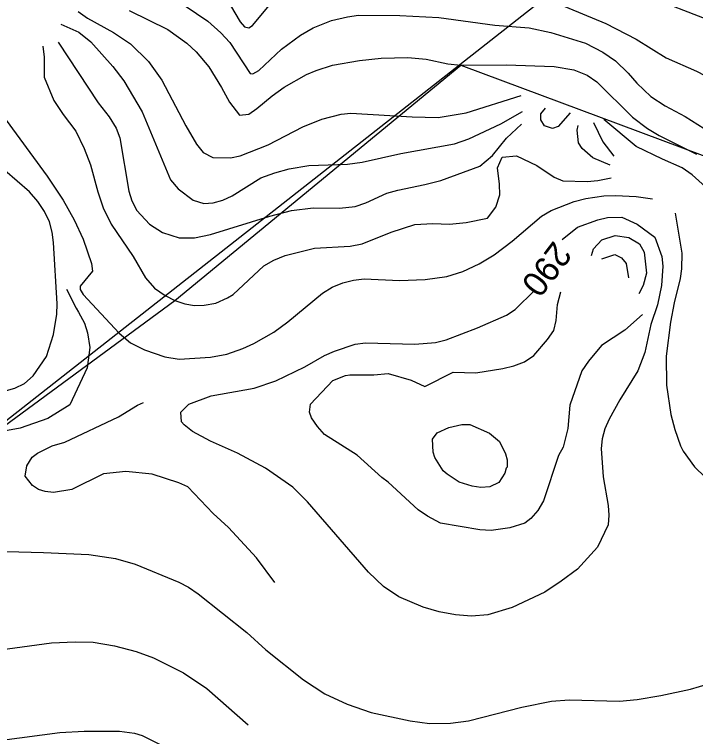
# Model space of a CAD drawing. Extents: x -662620 to -656370, y -1067090 to -1062990.
# Drawn here: x -661471.5 to -661109.4, y -1065594.8 to -1065210.9 of the extents above; entities that cross this region are included whole.
import ezdxf

# ---------------------------------------------------------------- set-up
doc = ezdxf.new("R2010")
doc.units = 0
for name, color, linetype in [('CHRANENE_LOZISKOVE_UZEMI', 7, 'Continuous'), ('HRANICE_KATASTRÁLNÍHO_ÚZEMÍ', 7, 'Continuous'), ('VRSTEVNICE_ZDŮRAZNĚNÁ', 7, 'Continuous'), ('VRSTEVNICE_ZDŮRAZNĚNÁ_-_POPIS', 7, 'Continuous'), ('VRSTEVNICE_ZÁKLADNÍ', 7, 'Continuous')]:
    doc.layers.add(name, color=color, linetype=linetype)

msp = doc.modelspace()

# ---------------------------------------------------------------- linework, layer by layer
at = {"layer": 'CHRANENE_LOZISKOVE_UZEMI'}
msp.add_lwpolyline([(-661096.57, -1065944.42), (-661652.65, -1065558.91), (-661386.13, -1065362.86), (-661234.18, -1065237.85), (-660862.53, -1065376.49), (-660732.31, -1065445.66), (-660264.34, -1065722.38)], dxfattribs=at)
at = {"layer": 'HRANICE_KATASTRÁLNÍHO_ÚZEMÍ'}
msp.add_lwpolyline([(-661678.37, -1065578.57), (-661652.65, -1065558.91), (-661530.81, -1065469.36), (-661523.21, -1065463.74), (-661084.87, -1065119.64)], dxfattribs=at)
at = {"layer": 'VRSTEVNICE_ZDŮRAZNĚNÁ'}
for points in [[(-661437.6, -1065209.33), (-661432.58, -1065212.77), (-661418.82, -1065220.51), (-661409.79, -1065226.53), (-661400.18, -1065235.85), (-661393.16, -1065245.74), (-661380.4, -1065270.11), (-661374.67, -1065279.86), (-661371.08, -1065284.3), (-661366.07, -1065286.88), (-661356.6, -1065287.17), (-661351.44, -1065286.02), (-661336.53, -1065280.14), (-661318.19, -1065270.68), (-661308.15, -1065266.53), (-661297.83, -1065263.8), (-661292.67, -1065263.37), (-661259.98, -1065265.38), (-661246.22, -1065265.67), (-661231.31, -1065263.23), (-661202.11, -1065254.02)], [(-661058.2, -1065396.19), (-661068.47, -1065386.44), (-661085.38, -1065351.53), (-661091.66, -1065335.79), (-661096.46, -1065319.61), (-661102.37, -1065304.17), (-661111.18, -1065296.06), (-661116.49, -1065292.33), (-661126.95, -1065287.89), (-661140.99, -1065281.09), (-661158.21, -1065266.68)], [(-661477.02, -1065411.17), (-661471.29, -1065409.59), (-661466.13, -1065407.01), (-661461.54, -1065403), (-661454.51, -1065392.68), (-661450.79, -1065381.07), (-661448.92, -1065370.17), (-661448.78, -1065364.72), (-661450.64, -1065332.04), (-661451.36, -1065326.59), (-661452.79, -1065321.14), (-661455.52, -1065315.7), (-661458.96, -1065310.25), (-661463.55, -1065305.09), (-661483.33, -1065288.17)], [(-661180.24, -1065330.57), (-661172.19, -1065323.92), (-661161.36, -1065320), (-661156.2, -1065318.85), (-661148.6, -1065318.71), (-661140.43, -1065322.29), (-661131.11, -1065329.31), (-661127.38, -1065339.49), (-661126.81, -1065344.65), (-661127.52, -1065354.98), (-661129.67, -1065365.3), (-661133.11, -1065375.62), (-661136.41, -1065390.53), (-661140, -1065400.27), (-661149.6, -1065415.76), (-661155.34, -1065426.08), (-661157.63, -1065431.24), (-661159.06, -1065436.4), (-661159.64, -1065441.56), (-661158.49, -1065456.76), (-661155.91, -1065471.95), (-661155.48, -1065477.11), (-661155.77, -1065482.27), (-661161.45, -1065494.1), (-661172.17, -1065505.7), (-661180.85, -1065512.23), (-661189.45, -1065517.97), (-661206.94, -1065526.14), (-661219.84, -1065530.01), (-661228.45, -1065530.73), (-661237.05, -1065530.01), (-661245.65, -1065528.43), (-661254.25, -1065526), (-661267.15, -1065520.55), (-661275.32, -1065514.96), (-661283.35, -1065507.36), (-661315.75, -1065469.94), (-661323.49, -1065462.2), (-661337.97, -1065452.03), (-661352.88, -1065444.14), (-661367.21, -1065437.69), (-661376.82, -1065432.67), (-661381.26, -1065429.09), (-661382.69, -1065427.37), (-661382.99, -1065422.27), (-661378.78, -1065418.06), (-661366.93, -1065413.61), (-661343.99, -1065409.59), (-661332.52, -1065405.72), (-661317.04, -1065398.12), (-661306.57, -1065392.25), (-661301.27, -1065389.81), (-661290.37, -1065386.23), (-661284.93, -1065385.37), (-661258.55, -1065386.23), (-661247.65, -1065385.22), (-661241.92, -1065383.79), (-661225.29, -1065377.48), (-661209.95, -1065370.74), (-661205.22, -1065367.73), (-661194.76, -1065357.41)]]:
    msp.add_lwpolyline(points, dxfattribs=at)
at = {"layer": 'VRSTEVNICE_ZÁKLADNÍ'}
for points in [[(-661189.17, -1065202.16), (-661157.05, -1065215.63), (-661141, -1065224.09), (-661124.94, -1065233.98), (-661108.89, -1065241.01), (-661095.99, -1065247.75), (-661065.17, -1065267.39), (-661059.72, -1065272.4), (-661051.55, -1065282.87), (-661046.02, -1065293.94)], [(-661189.17, -1065202.16), (-661157.05, -1065215.63), (-661141, -1065224.09), (-661124.94, -1065233.98), (-661108.89, -1065241.01), (-661095.99, -1065247.75), (-661065.17, -1065267.39), (-661059.72, -1065272.4), (-661051.55, -1065282.87), (-661046.02, -1065293.94)], [(-661040.29, -1065245.82), (-661048.12, -1065237.81), (-661060.15, -1065229.25), (-661067.89, -1065225.53), (-661102.29, -1065213.91), (-661134.41, -1065201.3)], [(-661040.29, -1065245.82), (-661048.12, -1065237.81), (-661060.15, -1065229.25), (-661067.89, -1065225.53), (-661102.29, -1065213.91), (-661134.41, -1065201.3)], [(-661356.6, -1065206.17), (-661351.44, -1065214.77), (-661349.15, -1065217.5), (-661346.86, -1065217.93), (-661344.99, -1065216.78), (-661334.1, -1065203.74)], [(-661356.6, -1065206.17), (-661351.44, -1065214.77), (-661349.15, -1065217.5), (-661346.86, -1065217.93), (-661344.99, -1065216.78), (-661334.1, -1065203.74)], [(-661410.51, -1065208.75), (-661389.86, -1065218.93), (-661379.83, -1065226.1), (-661374.81, -1065230.83), (-661368.22, -1065238.71), (-661361.33, -1065249.75), (-661357.18, -1065257.49), (-661351.87, -1065264.38), (-661346.86, -1065263.8), (-661342.56, -1065260.93), (-661334.53, -1065254.2), (-661328.08, -1065249.61), (-661316.18, -1065242.87), (-661311.02, -1065240.58), (-661302.42, -1065237.85), (-661288.08, -1065235.27), (-661276.61, -1065234.13), (-661262.28, -1065233.7), (-661252.53, -1065234.7), (-661241.06, -1065237.14), (-661234.18, -1065237.85), (-661210.1, -1065237.57), (-661184.58, -1065238.57), (-661174.18, -1065240.23), (-661167.08, -1065243.19), (-661161.93, -1065246.74), (-661142.86, -1065265.52), (-661134.98, -1065271.54), (-661128.81, -1065275.27), (-661108.89, -1065285.16)], [(-661410.51, -1065208.75), (-661389.86, -1065218.93), (-661379.83, -1065226.1), (-661374.81, -1065230.83), (-661368.22, -1065238.71), (-661361.33, -1065249.75), (-661357.18, -1065257.49), (-661351.87, -1065264.38), (-661346.86, -1065263.8), (-661342.56, -1065260.93), (-661334.53, -1065254.2), (-661328.08, -1065249.61), (-661316.18, -1065242.87), (-661311.02, -1065240.58), (-661302.42, -1065237.85), (-661288.08, -1065235.27), (-661276.61, -1065234.13), (-661262.28, -1065233.7), (-661252.53, -1065234.7), (-661241.06, -1065237.14), (-661234.18, -1065237.85), (-661210.1, -1065237.57), (-661184.58, -1065238.57), (-661174.18, -1065240.23), (-661167.08, -1065243.19), (-661161.93, -1065246.74), (-661142.86, -1065265.52), (-661134.98, -1065271.54), (-661128.81, -1065275.27), (-661108.89, -1065285.16)], [(-661380.69, -1065206.32), (-661368.65, -1065214.49), (-661361.76, -1065220.65), (-661357.03, -1065225.81), (-661346.14, -1065242.3), (-661344.71, -1065242.44), (-661341.55, -1065240.58), (-661329.51, -1065229.4), (-661319.33, -1065221.94), (-661312.59, -1065217.93), (-661302.99, -1065214.06), (-661294.39, -1065212.05), (-661288.65, -1065211.33), (-661266.58, -1065211.48), (-661245.93, -1065212.48), (-661216.12, -1065216.49), (-661197.77, -1065217.93), (-661186.3, -1065220.51), (-661167.95, -1065226.1), (-661158.78, -1065230.97), (-661152.04, -1065235.56), (-661145.16, -1065242.01), (-661140.57, -1065247.32), (-661133.11, -1065254.48), (-661125.52, -1065259.5), (-661114.91, -1065265.09), (-661104.87, -1065271.54)], [(-661380.69, -1065206.32), (-661368.65, -1065214.49), (-661361.76, -1065220.65), (-661357.03, -1065225.81), (-661346.14, -1065242.3), (-661344.71, -1065242.44), (-661341.55, -1065240.58), (-661329.51, -1065229.4), (-661319.33, -1065221.94), (-661312.59, -1065217.93), (-661302.99, -1065214.06), (-661294.39, -1065212.05), (-661288.65, -1065211.33), (-661266.58, -1065211.48), (-661245.93, -1065212.48), (-661216.12, -1065216.49), (-661197.77, -1065217.93), (-661186.3, -1065220.51), (-661167.95, -1065226.1), (-661158.78, -1065230.97), (-661152.04, -1065235.56), (-661145.16, -1065242.01), (-661140.57, -1065247.32), (-661133.11, -1065254.48), (-661125.52, -1065259.5), (-661114.91, -1065265.09), (-661104.87, -1065271.54)], [(-661446.78, -1065216.1), (-661437.23, -1065220.36), (-661430.79, -1065225.47), (-661419.25, -1065238.57), (-661413.37, -1065246.17), (-661403.62, -1065262.66), (-661388.43, -1065298.78), (-661384.41, -1065303.65), (-661376.39, -1065309.54), (-661370.84, -1065311.39), (-661365.78, -1065310.97), (-661360.62, -1065309.68), (-661355.74, -1065307.24), (-661340.41, -1065297.78), (-661333.09, -1065295.05), (-661325.35, -1065292.9), (-661315.03, -1065291.18), (-661294.39, -1065290.47), (-661286.65, -1065289.32), (-661266, -1065284.73), (-661237.62, -1065279.57), (-661229.88, -1065276.99), (-661212.96, -1065268.96), (-661201.39, -1065262.5)], [(-661446.78, -1065216.1), (-661437.23, -1065220.36), (-661430.79, -1065225.47), (-661419.25, -1065238.57), (-661413.37, -1065246.17), (-661403.62, -1065262.66), (-661388.43, -1065298.78), (-661384.41, -1065303.65), (-661376.39, -1065309.54), (-661370.84, -1065311.39), (-661365.78, -1065310.97), (-661360.62, -1065309.68), (-661355.74, -1065307.24), (-661340.41, -1065297.78), (-661333.09, -1065295.05), (-661325.35, -1065292.9), (-661315.03, -1065291.18), (-661294.39, -1065290.47), (-661286.65, -1065289.32), (-661266, -1065284.73), (-661237.62, -1065279.57), (-661229.88, -1065276.99), (-661212.96, -1065268.96), (-661201.39, -1065262.5)], [(-661456.35, -1065227.79), (-661455.61, -1065233.56), (-661455.76, -1065244.22), (-661450.5, -1065256.63), (-661445.63, -1065264.09), (-661438.89, -1065272.98), (-661434.45, -1065282.15), (-661431, -1065290.75), (-661427.13, -1065305.09), (-661424.27, -1065313.69), (-661420.11, -1065322.29), (-661408.35, -1065339.49), (-661401.76, -1065350.96), (-661397.03, -1065356.41), (-661391.29, -1065360.28), (-661386.13, -1065362.86), (-661380.97, -1065364.72), (-661375.81, -1065365.58), (-661370.65, -1065365.44), (-661364.35, -1065364.29), (-661358.18, -1065361.57), (-661355.17, -1065359.71), (-661338.83, -1065344.51), (-661333.67, -1065341.5), (-661327.65, -1065339.06), (-661311.88, -1065335.19), (-661292.96, -1065334.05), (-661286.65, -1065332.9), (-661271.17, -1065326.59), (-661258.55, -1065322.58), (-661249.09, -1065322), (-661240.2, -1065322.43), (-661231.31, -1065321.43), (-661219.99, -1065319.14), (-661215.54, -1065313.26), (-661213.39, -1065306.81), (-661213.54, -1065301.07), (-661214.68, -1065292.47), (-661212.25, -1065286.74), (-661204.65, -1065286.02), (-661193.75, -1065291.18), (-661184.58, -1065297.35), (-661179.99, -1065299.35), (-661167.09, -1065299.64), (-661161.36, -1065299.07), (-661154.24, -1065297.64)], [(-661456.35, -1065227.79), (-661455.61, -1065233.56), (-661455.76, -1065244.22), (-661450.5, -1065256.63), (-661445.63, -1065264.09), (-661438.89, -1065272.98), (-661434.45, -1065282.15), (-661431, -1065290.75), (-661427.13, -1065305.09), (-661424.27, -1065313.69), (-661420.11, -1065322.29), (-661408.35, -1065339.49), (-661401.76, -1065350.96), (-661397.03, -1065356.41), (-661391.29, -1065360.28), (-661386.13, -1065362.86), (-661380.97, -1065364.72), (-661375.81, -1065365.58), (-661370.65, -1065365.44), (-661364.35, -1065364.29), (-661358.18, -1065361.57), (-661355.17, -1065359.71), (-661338.83, -1065344.51), (-661333.67, -1065341.5), (-661327.65, -1065339.06), (-661311.88, -1065335.19), (-661292.96, -1065334.05), (-661286.65, -1065332.9), (-661271.17, -1065326.59), (-661258.55, -1065322.58), (-661249.09, -1065322), (-661240.2, -1065322.43), (-661231.31, -1065321.43), (-661219.99, -1065319.14), (-661215.54, -1065313.26), (-661213.39, -1065306.81), (-661213.54, -1065301.07), (-661214.68, -1065292.47), (-661212.25, -1065286.74), (-661204.65, -1065286.02), (-661193.75, -1065291.18), (-661184.58, -1065297.35), (-661179.99, -1065299.35), (-661167.09, -1065299.64), (-661161.36, -1065299.07), (-661154.24, -1065297.64)], [(-661448.23, -1065225.61), (-661426.99, -1065257.78), (-661421.11, -1065265.24), (-661417.39, -1065271.26), (-661415.52, -1065276.42), (-661410.65, -1065304.8), (-661409.07, -1065309.96), (-661406.49, -1065315.12), (-661399.75, -1065322.43), (-661392.73, -1065326.73), (-661383.84, -1065329.6), (-661375.81, -1065329.6), (-661367.21, -1065327.88), (-661335.67, -1065318.13), (-661324.21, -1065315.12), (-661312.74, -1065313.69), (-661298.69, -1065313.83), (-661290.37, -1065312.97), (-661284.64, -1065310.96), (-661273.46, -1065305.95), (-661267.72, -1065304.23), (-661253.39, -1065301.36), (-661244.79, -1065299.07), (-661224.15, -1065291.61), (-661217.41, -1065285.88), (-661209.95, -1065276.7), (-661201.92, -1065269.11)], [(-661448.23, -1065225.61), (-661426.99, -1065257.78), (-661421.11, -1065265.24), (-661417.39, -1065271.26), (-661415.52, -1065276.42), (-661410.65, -1065304.8), (-661409.07, -1065309.96), (-661406.49, -1065315.12), (-661399.75, -1065322.43), (-661392.73, -1065326.73), (-661383.84, -1065329.6), (-661375.81, -1065329.6), (-661367.21, -1065327.88), (-661335.67, -1065318.13), (-661324.21, -1065315.12), (-661312.74, -1065313.69), (-661298.69, -1065313.83), (-661290.37, -1065312.97), (-661284.64, -1065310.96), (-661273.46, -1065305.95), (-661267.72, -1065304.23), (-661253.39, -1065301.36), (-661244.79, -1065299.07), (-661224.15, -1065291.61), (-661217.41, -1065285.88), (-661209.95, -1065276.7), (-661201.92, -1065269.11)], [(-661176.08, -1065263.19), (-661182.37, -1065270.52), (-661185.4, -1065271.48), (-661189.77, -1065270.11), (-661191.69, -1065266.93), (-661191.62, -1065263.67), (-661189.1, -1065260.71)], [(-661176.08, -1065263.19), (-661182.37, -1065270.52), (-661185.4, -1065271.48), (-661189.77, -1065270.11), (-661191.69, -1065266.93), (-661191.62, -1065263.67), (-661189.1, -1065260.71)], [(-661477.74, -1065264.38), (-661454.08, -1065296.77), (-661445.63, -1065309.68), (-661439.75, -1065320), (-661435.02, -1065330.32), (-661430.57, -1065343.22), (-661430, -1065347.38), (-661436.6, -1065355.4), (-661436.45, -1065357.13), (-661435.02, -1065359.71), (-661415.81, -1065380.35), (-661409.79, -1065385.37), (-661402.33, -1065389.09), (-661391.58, -1065392.82), (-661383.84, -1065394.11), (-661367.21, -1065393.11), (-661358.61, -1065391.53), (-661350.01, -1065388.52), (-661344.28, -1065385.8), (-661333.67, -1065379.77), (-661326.07, -1065374.33), (-661307.72, -1065358.99), (-661302.56, -1065355.84), (-661296.97, -1065353.54), (-661291.23, -1065352.11), (-661285.5, -1065351.39), (-661266.86, -1065352.39), (-661253.1, -1065351.82), (-661241.63, -1065350.1), (-661233.03, -1065347.52), (-661224.43, -1065343.51), (-661216.4, -1065338.63), (-661206.94, -1065331.32), (-661191.32, -1065318.13), (-661186.16, -1065315.12), (-661173.97, -1065310.39), (-661167.66, -1065308.67), (-661158.2, -1065307.24), (-661151.89, -1065307.09), (-661141, -1065307.67), (-661132.33, -1065308.93)], [(-661477.74, -1065264.38), (-661454.08, -1065296.77), (-661445.63, -1065309.68), (-661439.75, -1065320), (-661435.02, -1065330.32), (-661430.57, -1065343.22), (-661430, -1065347.38), (-661436.6, -1065355.4), (-661436.45, -1065357.13), (-661435.02, -1065359.71), (-661415.81, -1065380.35), (-661409.79, -1065385.37), (-661402.33, -1065389.09), (-661391.58, -1065392.82), (-661383.84, -1065394.11), (-661367.21, -1065393.11), (-661358.61, -1065391.53), (-661350.01, -1065388.52), (-661344.28, -1065385.8), (-661333.67, -1065379.77), (-661326.07, -1065374.33), (-661307.72, -1065358.99), (-661302.56, -1065355.84), (-661296.97, -1065353.54), (-661291.23, -1065352.11), (-661285.5, -1065351.39), (-661266.86, -1065352.39), (-661253.1, -1065351.82), (-661241.63, -1065350.1), (-661233.03, -1065347.52), (-661224.43, -1065343.51), (-661216.4, -1065338.63), (-661206.94, -1065331.32), (-661191.32, -1065318.13), (-661186.16, -1065315.12), (-661173.97, -1065310.39), (-661167.66, -1065308.67), (-661158.2, -1065307.24), (-661151.89, -1065307.09), (-661141, -1065307.67), (-661132.33, -1065308.93)], [(-661154.83, -1065291.05), (-661164.08, -1065287.06), (-661169.67, -1065282.15), (-661171.68, -1065279.14), (-661172.25, -1065272.4), (-661171.82, -1065269.97)], [(-661154.83, -1065291.05), (-661164.08, -1065287.06), (-661169.67, -1065282.15), (-661171.68, -1065279.14), (-661172.25, -1065272.4), (-661171.82, -1065269.97)], [(-661163.61, -1065268.3), (-661158.77, -1065278.64), (-661152.84, -1065286.15)], [(-661163.61, -1065268.3), (-661158.77, -1065278.64), (-661152.84, -1065286.15)], [(-661120.27, -1065316.44), (-661116.64, -1065337.83), (-661116.92, -1065346.09), (-661117.63, -1065351.25), (-661120.79, -1065364.15), (-661122.65, -1065374.47), (-661124.94, -1065392.53), (-661124.8, -1065408.02), (-661122.51, -1065423.5), (-661120.5, -1065431.53), (-661117.49, -1065440.13), (-661116.06, -1065442.99), (-661109.89, -1065451.45), (-661104.3, -1065456.9), (-661091.11, -1065467.65), (-661078.23, -1065480.37), (-661069.63, -1065492.12)], [(-661120.27, -1065316.44), (-661116.64, -1065337.83), (-661116.92, -1065346.09), (-661117.63, -1065351.25), (-661120.79, -1065364.15), (-661122.65, -1065374.47), (-661124.94, -1065392.53), (-661124.8, -1065408.02), (-661122.51, -1065423.5), (-661120.5, -1065431.53), (-661117.49, -1065440.13), (-661116.06, -1065442.99), (-661109.89, -1065451.45), (-661104.3, -1065456.9), (-661091.11, -1065467.65), (-661078.23, -1065480.37), (-661069.63, -1065492.12)], [(-661164.63, -1065338.97), (-661163.74, -1065335.45), (-661159.23, -1065330.64), (-661152.05, -1065328.35), (-661144.95, -1065329.46), (-661139.17, -1065332.75), (-661136.73, -1065337.19), (-661135.55, -1065348.44), (-661137.17, -1065354.99), (-661139.54, -1065359.36)], [(-661164.63, -1065338.97), (-661163.74, -1065335.45), (-661159.23, -1065330.64), (-661152.05, -1065328.35), (-661144.95, -1065329.46), (-661139.17, -1065332.75), (-661136.73, -1065337.19), (-661135.55, -1065348.44), (-661137.17, -1065354.99), (-661139.54, -1065359.36)], [(-661159.31, -1065340.71), (-661152.35, -1065338.49), (-661148.8, -1065340.34), (-661146.21, -1065343.23), (-661145.09, -1065350.92)], [(-661159.31, -1065340.71), (-661152.35, -1065338.49), (-661148.8, -1065340.34), (-661146.21, -1065343.23), (-661145.09, -1065350.92)], [(-661443.72, -1065356.84), (-661438.68, -1065367.06), (-661437.45, -1065369.17), (-661434.3, -1065375.05), (-661432.58, -1065380.21), (-661431.43, -1065387.95), (-661432.87, -1065398.7), (-661442.01, -1065418.35), (-661453.78, -1065425.72), (-661468.42, -1065430.81), (-661483.19, -1065433.53), (-661500.99, -1065440.82), (-661516.75, -1065441.6), (-661542.25, -1065440.41)], [(-661137.69, -1065370.33), (-661147.01, -1065378.77), (-661159.35, -1065386.94), (-661166.23, -1065395.11), (-661169.81, -1065400.42), (-661176.22, -1065418.66), (-661177.27, -1065430.95), (-661179.7, -1065440.99), (-661182.29, -1065445.43), (-661190.17, -1065469.37), (-661193.32, -1065474.53), (-661197.05, -1065478.83), (-661200.2, -1065481.27), (-661208.09, -1065483.85), (-661218.12, -1065485.14), (-661224.15, -1065484.85), (-661244.95, -1065481.34), (-661251.95, -1065477.54), (-661256.83, -1065474.25), (-661272.74, -1065459.48), (-661276.18, -1065457.04), (-661289.32, -1065445.24), (-661306.57, -1065434.11), (-661310.44, -1065429.95), (-661313.6, -1065425.36), (-661314.6, -1065422.35), (-661314.17, -1065418.05), (-661302.27, -1065405.48), (-661295.53, -1065402.86), (-661293.24, -1065402.43), (-661280.34, -1065402.43), (-661272.8, -1065401.73), (-661260.51, -1065405.21), (-661253.24, -1065408.59), (-661238.19, -1065401), (-661226.27, -1065401.48), (-661211.82, -1065399.13), (-661206.08, -1065397.7), (-661200.35, -1065395.54), (-661195.33, -1065392.25), (-661188.02, -1065383.65), (-661184.72, -1065378.92), (-661183.58, -1065373.61), (-661182.71, -1065365.01), (-661180.99, -1065358.27)], [(-661333.1, -1065512.88), (-661342.84, -1065499.76), (-661357.61, -1065483.71), (-661365.92, -1065476.25), (-661379.28, -1065462.08), (-661384.13, -1065459.91), (-661398.18, -1065455.32), (-661412.22, -1065453.89), (-661424.12, -1065455.04), (-661440.89, -1065463.44), (-661450.64, -1065464.93), (-661455.23, -1065464.5), (-661458.67, -1065463.49), (-661461.83, -1065461.34), (-661465.79, -1065456.35), (-661464.9, -1065450.8), (-661462.11, -1065446.29), (-661459.24, -1065444.14), (-661451.36, -1065440.27), (-661444.62, -1065438.26), (-661416.24, -1065424.79), (-661406.06, -1065418.63), (-661402.91, -1065417.19)], [(-661248.8, -1065443.57), (-661249.23, -1065436.69), (-661246.83, -1065433.32), (-661240.54, -1065430.51), (-661233.61, -1065428.95), (-661229.45, -1065428.8), (-661218.98, -1065433.53), (-661213.68, -1065437.98), (-661210.38, -1065444.43), (-661209.52, -1065447.58), (-661209.52, -1065451.6), (-661210.1, -1065452.03), (-661210.81, -1065454.75), (-661213.93, -1065459.62), (-661218.84, -1065461.92), (-661223.57, -1065462.35), (-661228.16, -1065461.63), (-661235.04, -1065459.48), (-661241.49, -1065455.32), (-661243.5, -1065453.46), (-661247.94, -1065446.43), (-661248.8, -1065443.57)], [(-661248.8, -1065443.57), (-661249.23, -1065436.69), (-661246.83, -1065433.32), (-661240.54, -1065430.51), (-661233.61, -1065428.95), (-661229.45, -1065428.8), (-661218.98, -1065433.53), (-661213.68, -1065437.98), (-661210.38, -1065444.43), (-661209.52, -1065447.58), (-661209.52, -1065451.6), (-661210.1, -1065452.03), (-661210.81, -1065454.75), (-661213.93, -1065459.62), (-661218.84, -1065461.92), (-661223.57, -1065462.35), (-661228.16, -1065461.63), (-661235.04, -1065459.48), (-661241.49, -1065455.32), (-661243.5, -1065453.46), (-661247.94, -1065446.43), (-661248.8, -1065443.57)], [(-661502.25, -1065495.75), (-661456.09, -1065496.9), (-661432.01, -1065498.04), (-661417.67, -1065500.19), (-661407.35, -1065503.06), (-661384.13, -1065512.66), (-661378.97, -1065515.39), (-661373.81, -1065518.83), (-661348, -1065539.47), (-661337.82, -1065548.65), (-661317.75, -1065564.56), (-661306.43, -1065572.01), (-661294.68, -1065577.6), (-661281.77, -1065581.9), (-661261.13, -1065586.49), (-661250.81, -1065587.78), (-661239.63, -1065587.64), (-661230.17, -1065586.49), (-661201.78, -1065579.18), (-661186.01, -1065575.88), (-661176.55, -1065575.31), (-661149.89, -1065575.88), (-661140.43, -1065575.02), (-661127.81, -1065573.02), (-661112.04, -1065569.58), (-661102.58, -1065566.71)], [(-661502.25, -1065495.75), (-661456.09, -1065496.9), (-661432.01, -1065498.04), (-661417.67, -1065500.19), (-661407.35, -1065503.06), (-661384.13, -1065512.66), (-661378.97, -1065515.39), (-661373.81, -1065518.83), (-661348, -1065539.47), (-661337.82, -1065548.65), (-661317.75, -1065564.56), (-661306.43, -1065572.01), (-661294.68, -1065577.6), (-661281.77, -1065581.9), (-661261.13, -1065586.49), (-661250.81, -1065587.78), (-661239.63, -1065587.64), (-661230.17, -1065586.49), (-661201.78, -1065579.18), (-661186.01, -1065575.88), (-661176.55, -1065575.31), (-661149.89, -1065575.88), (-661140.43, -1065575.02), (-661127.81, -1065573.02), (-661112.04, -1065569.58), (-661102.58, -1065566.71)], [(-661479.32, -1065548.65), (-661451.79, -1065544.92), (-661439.18, -1065544.35), (-661429.71, -1065544.63), (-661418.25, -1065546.5), (-661406.78, -1065549.51), (-661397.6, -1065552.95), (-661381.55, -1065560.97), (-661369.22, -1065569.15), (-661347.29, -1065588.5)], [(-661479.32, -1065548.65), (-661451.79, -1065544.92), (-661439.18, -1065544.35), (-661429.71, -1065544.63), (-661418.25, -1065546.5), (-661406.78, -1065549.51), (-661397.6, -1065552.95), (-661381.55, -1065560.97), (-661369.22, -1065569.15), (-661347.29, -1065588.5)], [(-661678.37, -1065565.77), (-661675.86, -1065567.97), (-661665.72, -1065574.11), (-661652.02, -1065578.39), (-661642.88, -1065579.39), (-661621.76, -1065579.67), (-661605.77, -1065581.25), (-661523.56, -1065598.66), (-661510.99, -1065599.8), (-661478.16, -1065596.66), (-661447.33, -1065592.66), (-661434.49, -1065591.81), (-661415.64, -1065591.81), (-661407.65, -1065592.95), (-661403.66, -1065594.23), (-661379.68, -1065606.22), (-661367.69, -1065609.51), (-661345.7, -1065612.36), (-661318.3, -1065614.08), (-661308.16, -1065613.5)], [(-661678.37, -1065565.77), (-661675.86, -1065567.97), (-661665.72, -1065574.11), (-661652.02, -1065578.39), (-661642.88, -1065579.39), (-661621.76, -1065579.67), (-661605.77, -1065581.25), (-661523.56, -1065598.66), (-661510.99, -1065599.8), (-661478.16, -1065596.66), (-661447.33, -1065592.66), (-661434.49, -1065591.81), (-661415.64, -1065591.81), (-661407.65, -1065592.95), (-661403.66, -1065594.23), (-661379.68, -1065606.22), (-661367.69, -1065609.51), (-661345.7, -1065612.36), (-661318.3, -1065614.08), (-661308.16, -1065613.5)]]:
    msp.add_lwpolyline(points, dxfattribs=at)

# ---------------------------------------------------------------- texts
at = {"layer": 'VRSTEVNICE_ZDŮRAZNĚNÁ_-_POPIS'}
msp.add_text('290', height=13.2, rotation=232.6433, dxfattribs=at).set_placement((-661184.77, -1065330.68))

doc.saveas('drawing.dxf')
